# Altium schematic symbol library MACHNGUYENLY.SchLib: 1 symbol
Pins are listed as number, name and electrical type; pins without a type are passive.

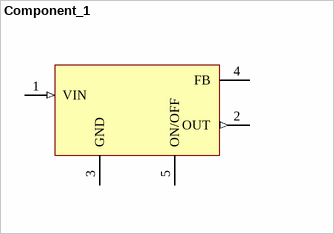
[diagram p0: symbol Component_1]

## Component_1
designator *
pins: 1 VIN (in), 2 OUT (out), 3 GND (power), 4 FB, 5 ON/OFF (power)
